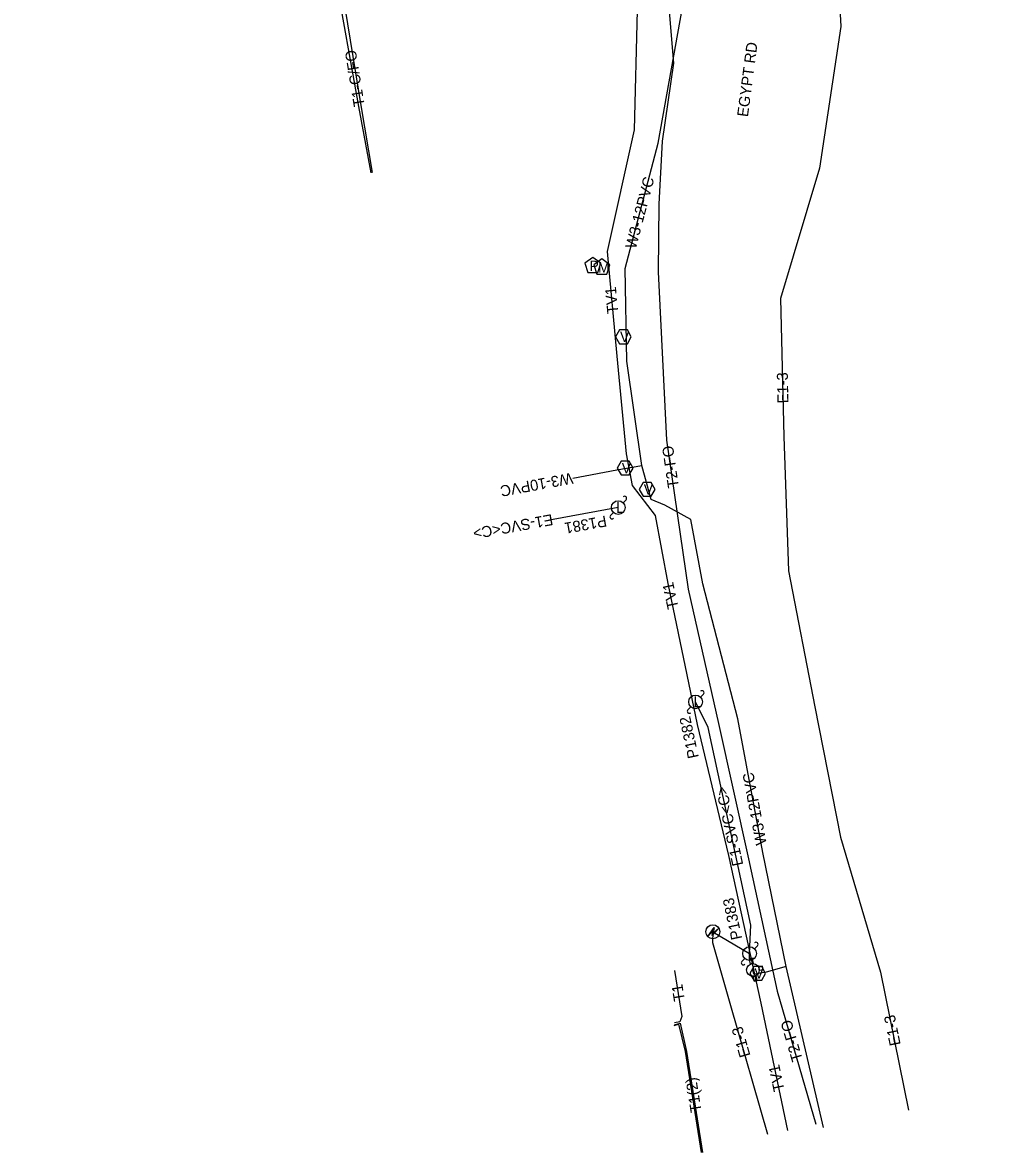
# Model space of a CAD drawing. Extents: x 2336688 to 2352634, y 362473 to 369571.
# Drawn here: x 2351896.3 to 2352253.1, y 368387.2 to 368798.3 of the extents above; entities that cross this region are included whole.
import ezdxf

# ---------------------------------------------------------------- set-up
doc = ezdxf.new("R2010")
doc.units = 0
for name, color, linetype in [('RD_EX_DV_Prop', 7, 'Continuous'), ('RD_EX_DV_TX_Prop', 7, 'Continuous'), ('RD_EX_RW', 7, 'Continuous'), ('RD_EX_RW_TX', 7, 'Continuous'), ('RD_HC_Data_Tic', 7, 'Continuous'), ('RD_PD_CstnLmt', 7, 'Continuous'), ('RD_PD_Final_TrvlWay', 7, 'Continuous'), ('RD_Sketch2', 7, 'Continuous'), ('RD_TX_Misc1', 7, 'Continuous')]:
    doc.layers.add(name, color=color, linetype=linetype)

msp = doc.modelspace()

# ---------------------------------------------------------------- linework, layer by layer
at = {"layer": 'RD_EX_RW_TX'}
for points in [[(2352023.04, 368743.58), (2352018.61, 368767.78), (2352010.03, 368815.88), (2352013.76, 368823.78), (2352034.6, 368860.37), (2352042.45, 368861.06), (2352052.12, 368870.24), (2352054.08, 368874.63), (2352055.88, 368877.58), (2352074.45, 368880.8), (2352091.57, 368884.28), (2352100.52, 368888.27), (2352100.36, 368883.74)], [(2352105.46, 368877.27), (2352105.38, 368876.27), (2352106.29, 368871.12), (2352112.27, 368856.3), (2352118.64, 368841.19), (2352119.94, 368802.65), (2352118.78, 368759.27), (2352108.98, 368715.07), (2352112.43, 368676.89), (2352115.93, 368641.39), (2352118.07, 368629.84), (2352126.4, 368618.98), (2352131.04, 368594.27), (2352141.76, 368542.92), (2352153.06, 368495.22), (2352164.89, 368441.51), (2352174.56, 368395.19)], [(2351800.26, 368708.59), (2351783.98, 368756.59), (2351767.48, 368792.11), (2351762.88, 368809.69), (2351759.04, 368825.42), (2351758.66, 368825.96), (2351759.26, 368827.23), (2351756.66, 368842.63), (2351785.44, 368848.99), (2351806.34, 368852.99), (2351854.03, 368859.38), (2351906.18, 368864.55), (2351953.78, 368869.16), (2351999.38, 368874.93), (2352002.29, 368863.43), (2352001.55, 368861.67), (2352003.47, 368859.64), (2352009.35, 368840.16), (2352015.45, 368822.2), (2352011.56, 368815.85), (2352019.33, 368768.13), (2352023.49, 368743.71)], [(2352128.32, 368840.02), (2352133.08, 368783.49), (2352128.94, 368755.14), (2352127.82, 368732.26), (2352127.55, 368707.56), (2352130.6, 368646.31), (2352138.42, 368592.19), (2352149.5, 368543.27), (2352160.43, 368493.98), (2352170.81, 368445.84), (2352184.93, 368397.48)], [(2352133.5, 368453.43), (2352136.17, 368436.61), (2352135.41, 368434.69), (2352133.47, 368434.4)], [(2352133.37, 368433.38), (2352134.92, 368433.87), (2352137.38, 368423.9), (2352143.16, 368387.23)], [(2352133.41, 368433.69), (2352135.47, 368434.2), (2352137.87, 368423.94), (2352143.67, 368387.21)]]:
    msp.add_lwpolyline(points, dxfattribs=at)
at = {"layer": 'RD_HC_Data_Tic'}
for p, q in [((2352114.76, 368623.6), (2352115.83, 368624.66)), ((2352110.17, 368619), (2352111.23, 368620.06)), ((2352142.92, 368552.87), (2352143.99, 368553.93)), ((2352138.33, 368548.27), (2352139.39, 368549.34)), ((2352162.57, 368461.32), (2352163.64, 368462.38)), ((2352157.98, 368456.72), (2352159.04, 368457.78))]:
    msp.add_line(p, q, dxfattribs=at)
for centre in [(2352113, 368621.83), (2352141.16, 368551.1), (2352160.81, 368459.55)]:
    msp.add_circle(centre, 2.5, dxfattribs=at)
for centre, start, end in [((2352115.3, 368625.19), 315, 135), ((2352110.7, 368618.47), 135, 315), ((2352143.46, 368554.46), 315, 135), ((2352138.86, 368547.74), 135, 315), ((2352163.11, 368462.91), 315, 135), ((2352158.51, 368456.19), 135, 315)]:
    msp.add_arc(centre, 0.75, start, end, dxfattribs=at)
at = {"layer": 'RD_PD_Final_TrvlWay'}
msp.add_line((2352113, 368621.83), (2352087.93, 368617.29), dxfattribs=at)
for points in [[(2352253.13, 368886.52), (2352236.2, 368880.33), (2352199.36, 368866.35), (2352190.99, 368861.65), (2352189.74, 368858.57), (2352191.19, 368848.42), (2352194.01, 368796.93), (2352186.25, 368745.32), (2352172.04, 368697.96), (2352173.22, 368647.74), (2352174.91, 368598.79), (2352184.51, 368549.35), (2352193.88, 368501.9), (2352208.42, 368452.8), (2352218.56, 368402.62)], [(2352147.41, 368467.51), (2352160.81, 368459.55), (2352161.19, 368469.86), (2352145.74, 368541.86), (2352141.16, 368551.1)], [(2352147.41, 368467.51), (2352147.32, 368463.61), (2352153.85, 368440.62), (2352167.28, 368393.84)]]:
    msp.add_lwpolyline(points, dxfattribs=at)
msp.add_lwpolyline([(2352149.54, 368468.79), (2352147.17, 368466.09), (2352147.51, 368468), (2352145.62, 368465.76), (2352147.9, 368469.01), (2352147.59, 368467.01)], close=True, dxfattribs=at)
msp.add_circle((2352147.41, 368467.51), 2.55, dxfattribs=at)
at = {"layer": 'RD_Sketch2'}
for p, q in [((2352161.8, 368457.69), (2352160.67, 368457.45)), ((2352160.67, 368457.45), (2352161.05, 368455.73)), ((2352162.18, 368455.94), (2352161.8, 368457.69)), ((2352165.53, 368454.94), (2352164.09, 368454.63)), ((2352164.31, 368453.49), (2352165.78, 368453.81)), ((2352165.78, 368453.81), (2352165.53, 368454.94)), ((2352162.01, 368451.32), (2352162.39, 368449.55)), ((2352162.39, 368449.55), (2352163.52, 368449.79)), ((2352163.52, 368449.79), (2352163.13, 368451.61))]:
    msp.add_line(p, q, dxfattribs=at)
for points in [[(2352187.62, 368396.3), (2352174.11, 368454.82), (2352165.61, 368496.3), (2352156.46, 368545.01), (2352143.73, 368594.08), (2352139.42, 368617.5), (2352129.98, 368622.67), (2352124.98, 368624.79), (2352121.55, 368637.11), (2352116.12, 368675.06), (2352115.47, 368708.83), (2352127.49, 368754.37), (2352136.41, 368803.76), (2352134.42, 368841.72), (2352121.13, 368956.04), (2352120.89, 368957.46)], [(2352096.48, 368632.57), (2352112.51, 368635.52), (2352121.55, 368637.11)], [(2352174.11, 368454.82), (2352166.87, 368452.81), (2352162.59, 368452.09), (2352162.28, 368452.04), (2352162.01, 368453.63)]]:
    msp.add_lwpolyline(points, dxfattribs=at)
for points in [[(2352103.72, 368712.84), (2352100.82, 368710.74), (2352101.93, 368707.33), (2352105.51, 368707.33), (2352106.62, 368710.74)], [(2352107.05, 368712.3), (2352104.15, 368710.19), (2352105.26, 368706.78), (2352108.84, 368706.78), (2352109.95, 368710.19)], [(2352117.75, 368683.96), (2352116.31, 368686.46), (2352113.42, 368686.46), (2352111.98, 368683.96), (2352113.42, 368681.46), (2352116.31, 368681.46)], [(2352118.39, 368636.21), (2352116.94, 368638.71), (2352114.06, 368638.71), (2352112.61, 368636.21), (2352114.06, 368633.71), (2352116.94, 368633.71)], [(2352126.38, 368628.45), (2352124.93, 368630.95), (2352122.05, 368630.95), (2352120.6, 368628.45), (2352122.05, 368625.95), (2352124.93, 368625.95)], [(2352166.62, 368452.34), (2352165.18, 368454.84), (2352162.29, 368454.84), (2352160.85, 368452.34), (2352162.29, 368449.84), (2352165.18, 368449.84)]]:
    msp.add_lwpolyline(points, close=True, dxfattribs=at)
for radius in [2.31, 0.289]:
    msp.add_circle((2352162.01, 368453.63), radius, dxfattribs=at)
for start, end in [(85.6407, 114.617), (356.5475, 25.5147), (269.987, 298.9633)]:
    msp.add_arc((2352162.01, 368453.63), 2.31, start, end, dxfattribs=at)

# ---------------------------------------------------------------- texts
at = {"layer": 'RD_EX_DV_Prop'}
for s, rotation, p in [('E1-3', 91.3449, (2352174.94, 368659.79)), ('E1-SVC<C>', 190.258, (2352088.85, 368619.49)), ('E1-SVC<C>', 102.1139, (2352158.51, 368491.89)), ('E1-3', 101.4234, (2352215.78, 368426.45)), ('E1-3', 106.0228, (2352161.14, 368422.46))]:
    msp.add_text(s, height=4, rotation=rotation, dxfattribs=at).set_placement(p)
at = {"layer": 'RD_EX_DV_TX_Prop'}
for s, rotation, p in [('P1381', 190.258, (2352108.39, 368618.97)), ('P1382', 102.1139, (2352142.35, 368531.03)), ('P1383', 102.1139, (2352158.12, 368465.03))]:
    msp.add_text(s, height=4, rotation=rotation, dxfattribs=at).set_placement(p)
at = {"layer": 'RD_EX_RW'}
for s, rotation, p in [('T1-C/FO', 99.2404, (2352020.79, 368768.04)), ('TV1', 95.1771, (2352113.02, 368692.55)), ('T2-FO', 98.2297, (2352135.08, 368629.29)), ('TV1', 101.7952, (2352134.94, 368585.37)), ('T1', 99.0237, (2352137.26, 368442.54)), ('T2-FO', 106.2707, (2352180.16, 368420.96)), ('TV1', 101.796, (2352173.55, 368409.83)), ('T1(2)', 98.9721, (2352143.34, 368402.11))]:
    msp.add_text(s, height=4, rotation=rotation, dxfattribs=at).set_placement(p)
at = {"layer": 'RD_HC_Data_Tic'}
for p in [(2352112.19, 368619.9), (2352140.35, 368549.17), (2352160, 368457.62)]:
    msp.add_text('L', height=4, rotation=360, dxfattribs=at).set_placement(p)
at = {"layer": 'RD_PD_CstnLmt'}
for s, rotation, p in [('W3-12PVC', 75.2176, (2352119.35, 368715.71)), ('W3-10PVC', 190.4208, (2352096.08, 368634.53)), ('W3-12PVC', 100.6321, (2352167.05, 368499.44))]:
    msp.add_text(s, height=4, rotation=rotation, dxfattribs=at).set_placement(p)
at = {"layer": 'RD_Sketch2'}
msp.add_text('P', height=3.75, rotation=360, dxfattribs=at).set_placement((2352102.57, 368707.92))
for s, p in [('M', (2352105.68, 368707.26)), ('V', (2352113.65, 368682.09)), ('V', (2352114.29, 368634.33)), ('V', (2352122.28, 368626.57)), ('V', (2352162.53, 368450.47))]:
    msp.add_text(s, height=3.75, dxfattribs=at).set_placement(p)
at = {"layer": 'RD_TX_Misc1'}
msp.add_text('EGYPT RD', height=4, rotation=82.5442, dxfattribs=at).set_placement((2352160.17, 368763.81))

doc.saveas('drawing.dxf')
